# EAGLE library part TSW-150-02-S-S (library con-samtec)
THROUGH-HOLE .025" SQ POST HEADER Source: Samtec TSW.pdf
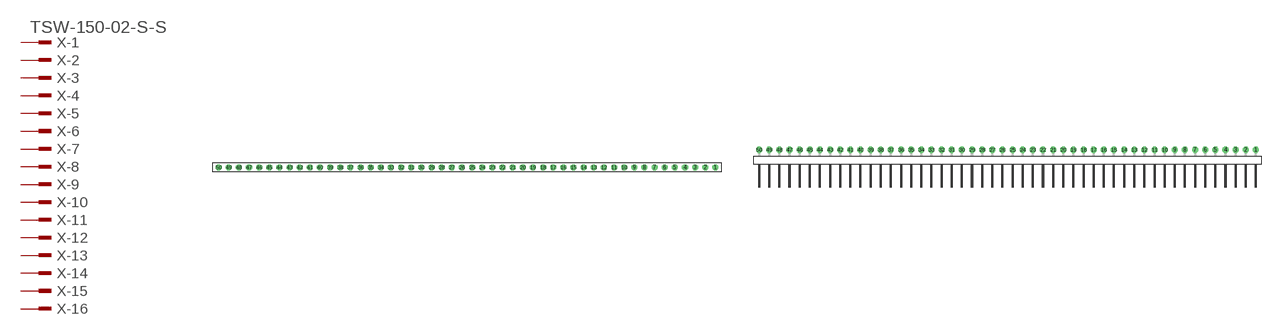
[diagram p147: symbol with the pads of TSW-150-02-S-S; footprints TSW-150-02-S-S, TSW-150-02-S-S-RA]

Designator prefix X; gates -1=MPINV -2=MPIN -3=MPIN -4=MPIN -5=MPIN -6=MPIN -7=MPIN -8=MPIN -9=MPIN -10=MPIN -11=MPIN -12=MPIN -13=MPIN -14=MPIN -15=MPIN -16=MPIN -17=MPIN -18=MPIN -19=MPIN -20=MPIN -21=MPIN -22=MPIN -23=MPIN -24=MPIN -25=MPIN -26=MPIN -27=MPIN -28=MPIN -29=MPIN -30=MPIN -31=MPIN -32=MPIN -33=MPIN -34=MPIN -35=MPIN -36=MPIN -37=MPIN -38=MPIN -39=MPIN -40=MPIN -41=MPIN -42=MPIN -43=MPIN -44=MPIN -45=MPIN -46=MPIN -47=MPIN -48=MPIN -49=MPIN -50=MPIN

## TSW-150-02-S-S (OC_FARNELL: unknown; OC_NEWARK: unknown)  [TSW-150-02-S-S]
1  -1:1  pas
2  -2:1  pas
3  -3:1  pas
4  -4:1  pas
5  -5:1  pas
6  -6:1  pas
7  -7:1  pas
8  -8:1  pas
9  -9:1  pas
10  -10:1  pas
11  -11:1  pas
12  -12:1  pas
13  -13:1  pas
14  -14:1  pas
15  -15:1  pas
16  -16:1  pas
17  -17:1  pas
18  -18:1  pas
19  -19:1  pas
20  -20:1  pas
21  -21:1  pas
22  -22:1  pas
23  -23:1  pas
24  -24:1  pas
25  -25:1  pas
26  -26:1  pas
27  -27:1  pas
28  -28:1  pas
29  -29:1  pas
30  -30:1  pas
31  -31:1  pas
32  -32:1  pas
33  -33:1  pas
34  -34:1  pas
35  -35:1  pas
36  -36:1  pas
37  -37:1  pas
38  -38:1  pas
39  -39:1  pas
40  -40:1  pas
41  -41:1  pas
42  -42:1  pas
43  -43:1  pas
44  -44:1  pas
45  -45:1  pas
46  -46:1  pas
47  -47:1  pas
48  -48:1  pas
49  -49:1  pas
50  -50:1  pas

## TSW-150-02-S-S-RA (OC_FARNELL: unknown; OC_NEWARK: unknown)  [TSW-150-02-S-S-RA]
Pads as for TSW-150-02-S-S

## Footprint TSW-150-02-S-S (pad centres in mm)
THROUGH-HOLE .025" SQ POST HEADER Source: Samtec TSW.pdf
drill 1 pad 1.5 octagon: 1 62.23,0; 2 59.69,0; 3 57.15,0; 4 54.61,0; 5 52.07,0; 6 49.53,0; 7 46.99,0; 8 44.45,0; 9 41.91,0; 10 39.37,0; 11 36.83,0; 12 34.29,0; 13 31.75,0; 14 29.21,0; 15 26.67,0; 16 24.13,0; 17 21.59,0; 18 19.05,0; 19 16.51,0; 20 13.97,0; 21 11.43,0; 22 8.89,0; 23 6.35,0; 24 3.81,0; 25 1.27,0; 26 -1.27,0; 27 -3.81,0; 28 -6.35,0; 29 -8.89,0; 30 -11.43,0; 31 -13.97,0; 32 -16.51,0; 33 -19.05,0; 34 -21.59,0; 35 -24.13,0; 36 -26.67,0; 37 -29.21,0; 38 -31.75,0; 39 -34.29,0; 40 -36.83,0; 41 -39.37,0; 42 -41.91,0; 43 -44.45,0; 44 -46.99,0; 45 -49.53,0; 46 -52.07,0; 47 -54.61,0; 48 -57.15,0; 49 -59.69,0; 50 -62.23,0

## Footprint TSW-150-02-S-S-RA (pad centres in mm)
THROUGH-HOLE .025" SQ POST HEADER Source: Samtec TSW.pdf
drill 1 pad 1.5 octagon: 1 62.23,1.524; 2 59.69,1.524; 3 57.15,1.524; 4 54.61,1.524; 5 52.07,1.524; 6 49.53,1.524; 7 46.99,1.524; 8 44.45,1.524; 9 41.91,1.524; 10 39.37,1.524; 11 36.83,1.524; 12 34.29,1.524; 13 31.75,1.524; 14 29.21,1.524; 15 26.67,1.524; 16 24.13,1.524; 17 21.59,1.524; 18 19.05,1.524; 19 16.51,1.524; 20 13.97,1.524; 21 11.43,1.524; 22 8.89,1.524; 23 6.35,1.524; 24 3.81,1.524; 25 1.27,1.524; 26 -1.27,1.524; 27 -3.81,1.524; 28 -6.35,1.524; 29 -8.89,1.524; 30 -11.43,1.524; 31 -13.97,1.524; 32 -16.51,1.524; 33 -19.05,1.524; 34 -21.59,1.524; 35 -24.13,1.524; 36 -26.67,1.524; 37 -29.21,1.524; 38 -31.75,1.524; 39 -34.29,1.524; 40 -36.83,1.524; 41 -39.37,1.524; 42 -41.91,1.524; 43 -44.45,1.524; 44 -46.99,1.524; 45 -49.53,1.524; 46 -52.07,1.524; 47 -54.61,1.524; 48 -57.15,1.524; 49 -59.69,1.524; 50 -62.23,1.524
